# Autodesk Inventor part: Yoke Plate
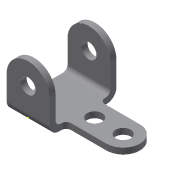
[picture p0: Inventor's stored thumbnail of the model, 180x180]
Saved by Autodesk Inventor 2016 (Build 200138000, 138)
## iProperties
Created: 2011-04
Part Number: Yoke Plate
Material: Generic
Document SubType Name: Modeling
Designer: Dell
Density: 1 g/cm^3
Appearance: Default
Author: Dell
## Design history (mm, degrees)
sketch "Sketch1"
  geometry: 1 further point
sketch "Sketch2"
  geometry: L1 (28.578, 36.513)-(28.483, -7.913); L2 (-28.517, -7.961)-(28.483, -7.913); L3 (-28.554, 36.476)-(-28.517, -7.961); C1 r 10 at (0.012, 36.5); A1 r 28.566 centre (0.012, 36.5) between (28.578, 36.513) and (-28.554, 36.476); 2 further points
  constraints: 6 end point, 2 centre point, 2 point on circle, 1 coincident, 1 perpendicular, 1 tangent, 1 other
  dimensions: "d0" = 57 distance of L2.start L1.end; "d1" = 36.5 distance of point (0, 0) C1.centre; "d2" = 28.5 distance from line of L1 point (0, 0); "d3" = 20 diameter of C1
extrude "Extrusion1" new body sketch "Sketch2" distance "d4" = 89; taper "d5" = 0 deg
sketch "Sketch3"
  geometry: L1 (44.437, 89)-(0, 89) reference; L2 (-28.588, 8)-(36.5, 8); L3 (36.5, 8)-(36.5, 81); L4 (36.5, 81)-(-28.588, 81); L5 (-28.588, 8)-(-28.588, 81); L6 (-28.566, 89)-(0.011, 89) reference; 3 further points
  constraints: 8 end point, 1 perpendicular
  dimensions: "d6" = 73 distance of L2.start L4.end; "d9" = 8 distance between parallel lines of L1 L4
extrude "Extrusion2" cut sketch "Sketch3" distance "d10" = 89; taper "d11" = 0 deg
sketch "Sketch4"
  geometry: L1 (0, 58.725)-(53.5, 58.725); L2 (53.5, 14.225)-(0, 14.225); L3 (0, 14.225)-(0, 58.725); C1 r 10 at (53.5, 36.475); C2 r 10 at (15.5, 36.513); A1 r 22.25 centre (53.5, 36.475) between (53.5, 14.225) and (53.5, 58.725); 1 further point
  constraints: 6 end point, 3 centre point, 2 point on circle, 1 coincident, 1 equal radius, 1 horizontal, 1 parallel, 1 perpendicular, 1 tangent
  dimensions: "d12" = 44.5 diameter of A1; "d13" = 44.5 distance between parallel lines of L2 L1; "d14" = 20 diameter of C1; "d15" = 38 distance of A1.centre C2.centre
extrude "Extrusion3" join sketch "Sketch4" stored distance "d16" = 89; taper "d17" = 0 deg
fillet "Fillet1" dims "d18" = 12.7
fillet "Fillet2" dims "d19" = 6.35
fillet "Fillet3" dims "d20" = 6.35
body "Solid1"
